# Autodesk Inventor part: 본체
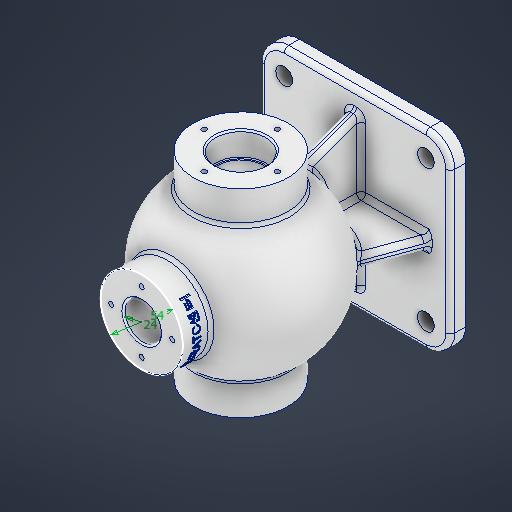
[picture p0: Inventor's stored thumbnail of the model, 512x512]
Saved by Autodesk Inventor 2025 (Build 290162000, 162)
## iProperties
Created: 2025-08
Part Number: 본체
Material: 알루미늄 6061
Document SubType Name: Modeling
Designer: infra012
Density: 2.7 g/cm^3
Appearance: 알루미늄 - 평지
Mass: 1540.2 g
Surface Area: 1173.87 cm^2
Volume: 570.444 cm^3
Author: infra012
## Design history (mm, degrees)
sketch "스케치2"
  geometry: L1 (-62.5, -62.5)-(62.5, -62.5); L2 (62.5, -62.5)-(62.5, 62.5); L3 (62.5, 62.5)-(-62.5, 62.5); L4 (-62.5, 62.5)-(-62.5, -62.5); L5 (-62.5, -62.5)-(62.5, 62.5); L6 (62.5, -62.5)-(-62.5, 62.5); 1 further point
  constraints: 12 end point, 2 midpoint, 2 parallel, 1 horizontal, 1 perpendicular
  dimensions: "d0" = 125 distance of L3.end L2.end; "d1" = 125 distance of L2.end L1.end
extrude "돌출1" new body sketch "스케치2" distance "d2" = 10; taper "d3" = 0 deg
sketch "스케치3"
  geometry: L1 (8.5, 85)-(116.5, 85); L2 (0, 0)-(125, 0) reference; A1 r 44 centre (62.5, 85) between (106.5, 85) and (18.5, 85); A2 r 54 centre (62.5, 85) between (116.5, 85) and (8.5, 85); 3 further points
  constraints: 4 point on circle, 2 centre point, 2 end point, 2 point on line, 1 coincident, 1 horizontal alignment, 1 midpoint
  dimensions: "d4" = 88 diameter of A1; "d5" = 108 diameter of A2; "d7" = 85 distance from line of L2 A1.centre
revolve "회전1" sketch "스케치3" stored, may be unused: angle "d8" = 90 deg
node "작업 평면1"
sketch "스케치4"
  geometry: C1 r 27 at (0, 0); C2 r 12 at (0, 0); 1 further point
  constraints: 2 centre point, 2 coincident
  dimensions: "d10" = 54 diameter of C1; "d11" = 24 diameter of C2
extrude "돌출2" join sketch "스케치4" stored distance "d12" = 10; taper "d13" = 0 deg
node "작업 평면3"
sketch "스케치5"
  geometry: L1 (-27, 131.765)-(27, 131.765) reference; C1 r 31 at (0, 85); A1 r 54 centre (0, 85) between (-27, 131.765) and (27, 131.765) reference; 1 further point
  constraints: 1 centre point, 1 coincident
  dimensions: "d16" = 62 diameter of C1
extrude "돌출3" join sketch "스케치5" stored distance "d18" = 10; taper "d19" = 0 deg
node "작업 평면4"
sketch "스케치6"
  geometry: C1 r 31 at (0, 85) reference; 1 further point
extrude "돌출4" join sketch "스케치6" stored distance "d21" = 10; taper "d22" = 0 deg
sketch "스케치7"
  geometry: C1 r 31 at (0, 0) reference; C2 r 15 at (0, 0); 1 further point
  constraints: 1 centre point, 1 coincident
  dimensions: "d23" = 30 diameter of C2
extrude "돌출5" cut sketch "스케치7" extent not by distance; stored distance "d24" = 0; taper "d25" = 0 deg
sketch "스케치8"
  geometry: C1 r 31 at (0, 0) reference; C2 r 16.5 at (0, 0); 1 further point
  constraints: 1 centre point, 1 coincident
  dimensions: "d26" = 33 diameter of C2
hole "구멍1" sketch "스케치8" at (0, 0) diameter "d27" = 33; stored, may be unused: countersink angle "d31" = 90 deg, drill point angle "d33" = 0 deg; dims "d28" = 12, "d29" = 33, "d30" = 1, "d32" = 16
sketch "스케치9"
  geometry: C1 r 16.5 at (0, 0) reference; 1 further point
hole "구멍2" sketch "스케치9" at (0, 0) diameter "d34" = 33; stored, may be unused: countersink angle "d38" = 90 deg, drill point angle "d40" = 0 deg; dims "d35" = 6, "d36" = 4, "d37" = 2, "d39" = 16
hole "구멍3" sketch "스케치4" diameter "d41" = 24; stored, may be unused: countersink angle "d45" = 90 deg, drill point angle "d47" = 0 deg; dims "d42" = 6, "d43" = 4, "d44" = 2, "d46" = 84.075
sketch "스케치11"
  geometry: L1 (-33.559, 56.544)-(-50.5, 10); L2 (33.559, 56.544)-(50.5, 10); L3 (-62.5, 0)-(-62.5, 10) reference; L4 (62.5, 0)-(62.5, 10) reference; L5 (62.5, 10)-(-62.5, 10) reference; A1 r 44 centre (0, 85) between (-41.364, 70) and (-41.364, 100) reference; 1 further point
  constraints: 4 end point, 2 point on circle, 2 point on line
  dimensions: "d48" = 20 deg angle of L3 L1; "d49" = 20 deg angle of L4 L2; "d50" = 12 distance from line of L1.end L3; "d51" = 12 distance from line of L4 L2.end
sketch "스케치12"
  geometry: L1 (-33.559, 56.544)-(-50.5, 10); L2 (33.559, 56.544)-(50.5, 10); L3 (-62.5, 0)-(-62.5, 10) reference; L4 (62.5, 0)-(62.5, 10) reference; L5 (62.5, 10)-(-62.5, 10) reference; A1 r 44 centre (0, 85) between (-12, 127.332) and (12, 127.332) reference; 1 further point
  constraints: 4 end point, 2 point on circle, 2 point on line
  dimensions: "d54" = 20 deg angle of L3 L1; "d55" = 20 deg angle of L4 L2; "d56" = 12 distance from line of L1.end L3; "d57" = 12 distance from line of L4 L2.end
sketch "스케치13" dims "d60" = 40
  geometry: L1 (0, 0)-(4, 4) reference; 5 further points
  constraints: 1 coincident, 1 horizontal alignment, 7 other
  dimensions: "d63" = 360 deg dimension on L1.start point (20, 0) (derived)
hole "구멍4" sketch "스케치13" at (20, 0), (0, -20), (-20, 0), (0, 20) diameter "d65" = 3.242; stored, may be unused: countersink angle "d69" = 90 deg, drill point angle "d71" = 118 deg; dims "d66" = 9, "d67" = 4, "d68" = 2, "d70" = 11
sketch "스케치14" dims "d72" = 48
  geometry: C1 r 15 at (0, 0) reference; 6 further points
  constraints: 1 coincident, 1 vertical alignment, 7 other
  dimensions: "d75" = 360 deg dimension on point (0, 0) point (0, -24) (derived)
hole "구멍5" sketch "스케치14" at (0, -24), (-24, 0), (0, 24), (24, 0) diameter "d77" = 3.242; stored, may be unused: countersink angle "d81" = 90 deg, drill point angle "d83" = 118 deg; dims "d78" = 12, "d79" = 4, "d80" = 2, "d82" = 15
sketch "스케치15"
  geometry: C1 r 1.621 at (0, 24) reference; C2 r 1.621 at (24, 0) reference; C3 r 1.621 at (-24, 0) reference; C4 r 1.621 at (0, -24) reference; 1 further point
hole "구멍6" sketch "스케치15" at (0, 24), (24, 0), (0, -24), (-24, 0) diameter "d84" = 3.242; stored, may be unused: countersink angle "d88" = 90 deg, drill point angle "d90" = 118 deg; dims "d85" = 12, "d86" = 4, "d87" = 2, "d89" = 15
fillet "모깎기1" dims "d91" = 16
fillet "모깎기4" dims "d94" = 3
sketch "스케치16"
  geometry: 1 further point
node "작업 평면5"
sketch "스케치17"
  geometry: L1 (-12.205, 145.584)-(12.205, 145.584); L2 (12.205, 145.584)-(12.205, 136.416); L3 (12.205, 136.416)-(-12.205, 136.416); L4 (-12.205, 136.416)-(-12.205, 145.584); L5 (27, 150)-(-27, 150) reference; 4 further points
  constraints: 3 midpoint, 1 vertical alignment, 2 other
  dimensions: "d96" = 9 distance from line of L5 point (-12.205, 141)
sketch "스케치18"
  geometry: L1 (46.5, 46.5)-(-46.5, 46.5); L2 (-46.5, 46.5)-(-46.5, -46.5); L3 (-46.5, -46.5)-(46.5, -46.5); L4 (46.5, -46.5)-(46.5, 46.5); L5 (46.5, 46.5)-(-46.5, -46.5); L6 (-46.5, 46.5)-(46.5, -46.5); 5 further points
  constraints: 12 end point, 4 coincident, 2 midpoint, 2 parallel, 1 horizontal, 1 perpendicular
  dimensions: "d102" = 93 distance of L3.end L2.end; "d103" = 93 distance of L2.end L1.end
hole "구멍7" sketch "스케치18" at (46.5, -46.5), (46.5, 46.5), (-46.5, 46.5), (-46.5, -46.5) diameter "d104" = 11; stored, may be unused: countersink angle "d108" = 90 deg, drill point angle "d110" = 118 deg; dims "d105" = 12, "d106" = 4, "d107" = 2, "d109" = 15
chamfer "모따기1" distance "d111" = 1; stored, may be unused: second distance "d112" = 2, angle "d113" = 45 deg
chamfer "모따기2" distance "d114" = 1; stored, may be unused: second distance "d115" = 2, angle "d116" = 45 deg
chamfer "모따기3" distance "d117" = 1; stored, may be unused: second distance "d118" = 2, angle "d119" = 45 deg
extrude "돌출8" join sketch "스케치11" stored distance "d120" = 8; taper "d121" = 0 deg
fillet "모깎기5" dims "d122" = 3
fillet "모깎기6" dims "d123" = 3
extrude "돌출9" join sketch "스케치12" stored distance "d125" = 8; taper "d126" = 0 deg
fillet "모깎기8" dims "d127" = 3
fillet "모깎기9" dims "d128" = 3
fillet "모깎기10" dims "d129" = 0.6
fillet "모깎기11" dims "d130" = 0.6
feature "엠보싱3" dims "d131" = 0.5, "d132" = 0
fillet "모깎기12" dims "d133" = 3
node "솔리드1"
node "투영된 루프1"
node "스케치 - 원형 패턴1" dims "d63" = 360 deg (derived)
node "스케치 - 원형 패턴2" dims "d75" = 360 deg (derived)
feature "A9D066F2-1C7D-4E18-AEED-F7BC21143FA4" dims "d27" = 33, "d28" = 12, "d29" = 33, "d30" = 1, "d31" = 90 deg, "d32" = 16, "d33" = 0
other parameters: "d15" = 65, "d20" = -65, "d95" = 62.5
